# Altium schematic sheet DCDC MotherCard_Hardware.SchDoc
size 431 x 279 mm; Date: Not shown in title block; ApprovedBy: Not shown in title block; CheckedBy: Not shown in title block; Author: Not shown in title block; CompanyName: Not shown in title block; DrawnBy: Forest Fu; Engineer: Not shown in title block; Organization: Not shown in title block; Address1: Not shown in title block; Address2: Not shown in title block; Address3: Not shown in title block; Address4: Not shown in title block; DocumentNumber: 3; Revision: Use project parameter SCH_Rev; SheetNumber: 5; SheetTotal: 5; PageSetup: Record=PageOptions¦CenterHorizontal=True¦CenterVertical=True¦PrintScale=1.00¦XCorrection=1.00¦YCorrection=1.00¦PrintKind=0¦BorderSize=5000000¦LeftOffset=0¦BottomOffset=0¦Orientation=2¦PaperLength=1000¦PaperWidth=1000¦Scale=100¦PaperSource=15¦PrintQuality=600¦MediaType=1¦DitherType=10¦PaperKind=Letter¦PrintScaleMode=1
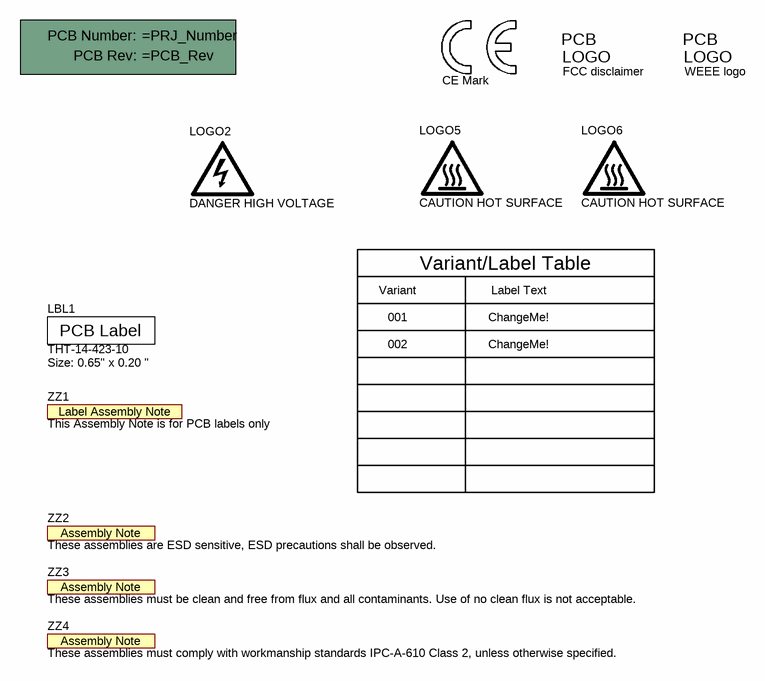
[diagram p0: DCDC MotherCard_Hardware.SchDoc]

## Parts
!PCB1  Printed Circuit Board  (value not drawn)  (mechanical)
LBL1  THT-14-423-10  Note: Size: 0.65" x 0.20 "  [Label_650x200]
Logo1  CE Mark  [CE_Mark_5mm]  (no BOM)
LOGO2  DANGER HIGH VOLTAGE  [IEC_HighVoltage_Small]  (no BOM)
Logo3  FCC disclaimer  [FCC_disclaimer]  (no BOM)
Logo4  WEEE logo  [WEEE_Minimum]  (no BOM)
LOGO5  CAUTION HOT SURFACE  [IEC_HotSurface_Small]  (no BOM)
LOGO6  CAUTION HOT SURFACE  [IEC_HotSurface_Small]  (no BOM)
ZZ1  This Assembly Note is for PCB labels only  [AssemblyNoteLabel]  (no BOM)
ZZ2  These assemblies are ESD sensitive, ESD precautions shall be observed.  [AssemblyNote]  (no BOM)
ZZ3  These assemblies must be clean and free from flux and all contaminants. Use of no clean flux is not acceptable.  [AssemblyNote]  (no BOM)
ZZ4  These assemblies must comply with workmanship standards IPC-A-610 Class 2, unless otherwise specified.  [AssemblyNote]  (no BOM)

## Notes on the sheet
- Variant
- Variant/Label Table
- Label Text
- 001
- 002
- ChangeMe!

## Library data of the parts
!PCB1 = CMP-0003618-2: Manufacturer: Any
LBL1 = CMP-0003625-1: Thermal Transfer Printable Labels, 0.650" W x 0.200" H - 10,000 per roll; Manufacturer: Brady; CompType: Label
Logo1 = CMP-0074844-1: SymbolCreator: a0412235
LOGO2 = CMP-0074835-1: IEC 61010-1 High Voltage Warning; SymbolCreator: a0412235
Logo3 = CMP-0074847-1: FCC_disclaimer; Library Reference: Logo
Logo4 = CMP-0074769-1
LOGO5 LOGO6 = CMP-0074837-1: IEC 61010-1 Hot Surface Warning; SymbolCreator: a0412235
ZZ1 = CMP-0003616-3
ZZ2 = CMP-0077236-1
ZZ3 = CMP-0077237-1
ZZ4 = CMP-0077238-1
